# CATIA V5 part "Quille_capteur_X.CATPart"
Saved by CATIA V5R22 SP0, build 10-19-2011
Part number: Quille_capteur_X
Bounding box of the stored display mesh (mm): x -35 to 35, y 0 to 45, z 0 to 10
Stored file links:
  U:\S9A\PER\CAO\Assemblage\Cadre\Chariot_X\Quille_capteur_X.CATPart
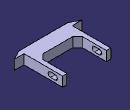
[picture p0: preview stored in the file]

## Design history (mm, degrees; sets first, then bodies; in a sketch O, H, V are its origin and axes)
Body1 (main body)
  Sketch1 on xy-plane, origin (0, 0, 0), H (1, 0, 0), V (0, 1, 0)
    line L1 (-25, 45) -> (-20.5, 45)
    line L2 (-20.5, 45) -> (-20.5, 15)
    point P3 (-20.5, 15)
    line L3 (-20.5, 15) -> (20.5, 15)
    point P4 (20.5, 15)
    line L4 (20.5, 15) -> (20.5, 45)
    point P5 (20.5, 45)
    line L5 (20.5, 45) -> (25, 45)
    line L6 (25, 45) -> (25, 5)
    line L7 (25, 5) -> (35, 5)
    line L8 (35, 5) -> (25, 0)
    point P9 (25, 0)
    line L9 (25, 0) -> (-25, 0)
    point P10 (-25, 0)
    line L10 (-25, 0) -> (-35, 5)
    line L11 (-35, 5) -> (-25, 5)
    point P12 (-25, 5)
    line L12 (-25, 5) -> (-25, 45)
    length L5 = 4.5
    length L1 = 4.5
    length L3 = 41
    length L4 = 30
    length L6 = 40
    length L12 = 40
    length L9 = 50
    length L7 = 10
    length L11 = 10
    distance P12 L9 = 5
    distance H L3 = 15
    horizontal: L1 H, L3 H, L5 H, L7 H, L9 H, L11 H
    vertical: L2 V, L4 V, L6 V, L12 V
    coincidence: P5 L1
    symmetry: P3 P4 V, P9 P10 V
  Pad1: profile Sketch1, direction (0, 0, 1), length 10
  Sketch2 on face of Pad1 from Sketch1.L6, origin (25, 0, 0), H (0, 1, 0), V (0, 0, 1)
    arc A1 centre (37.5, 5) radius 2.5 from (37.5, 2.5) to (37.5, 7.5) ccw
    point P1 (37.5, 5)
    reference projected line E1 (45, 0) -> (45, 10) from edge [face of Pad1 from Sketch1.L5 | face of Pad1 from Sketch1.L6]
    reference projected line E2 (5, 0) -> (45, 0) from edge [start face of Pad1 | face of Pad1 from Sketch1.L6]
    arc A2 centre (32.5, 5) radius 2.5 from (32.5, 7.5) to (32.5, 2.5) ccw
    axis line L1 (37.5, 5) -> (32.5, 5)
    line L2 (32.5, 7.5) -> (37.5, 7.5)
    line L3 (37.5, 2.5) -> (32.5, 2.5)
    radius A1 = 2.5
    distance P1 E1 = 7.5
    distance P1 E2 = 5
    radius A2 = 2.5
    length L1 = 5
    horizontal: L1 H
    tangency: L2 A1, L2 A2, L3 A1, L3 A2
  Pocket1: profile Sketch2, direction (-1, 0, 0), through (limit type 3)
  Chamfer1: length 5, angle 45, on edge [face of Pad1 from Sketch1.L2 | face of Pad1 from Sketch1.L3]; edge [face of Pad1 from Sketch1.L3 | face of Pad1 from Sketch1.L4]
